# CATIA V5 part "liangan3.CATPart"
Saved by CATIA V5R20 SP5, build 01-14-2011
Part number: 连杆3
Bounding box of the stored display mesh (mm): x -20 to 170, y -20 to 20, z 0 to 40
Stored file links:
  E:\scc\liangan\新建文件夹\liangan3.CATPart
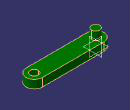
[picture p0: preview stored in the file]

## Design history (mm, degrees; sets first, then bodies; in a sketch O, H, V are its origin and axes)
Body1 (main body)
  Sketch1 on xy-plane, origin (0, 0, 0), H (1, 0, 0), V (0, 1, 0)
    construction line L1 (0, 0) -> (150, 0)
    line L2 (0, 20) -> (150, 20)
    line L3 (150, -20) -> (0, -20)
    arc A1 centre (150, 0) radius 20 from (150, 20) to (150, -20) cw
    arc A2 centre (0, 0) radius 20 from (0, -20) to (0, 20) cw
    circle A3 centre (150, 0) radius 10
    distance L1 L2 = 20
    radius A3 = 10
    horizontal: L1 H
    tangency: A1 L2, A2 L2, A1 L3, A2 L3
  Pad1: profile Sketch1, direction (0, 0, 1), length 20
  Sketch2 on end face of Pad1, origin (0, 0, 20), H (1, 0, 0), V (0, 1, 0)
    circle A1 centre (0, 0) radius 10
    radius A1 = 10
  Pad2: profile Sketch2, direction (0, 0, 1), length 20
